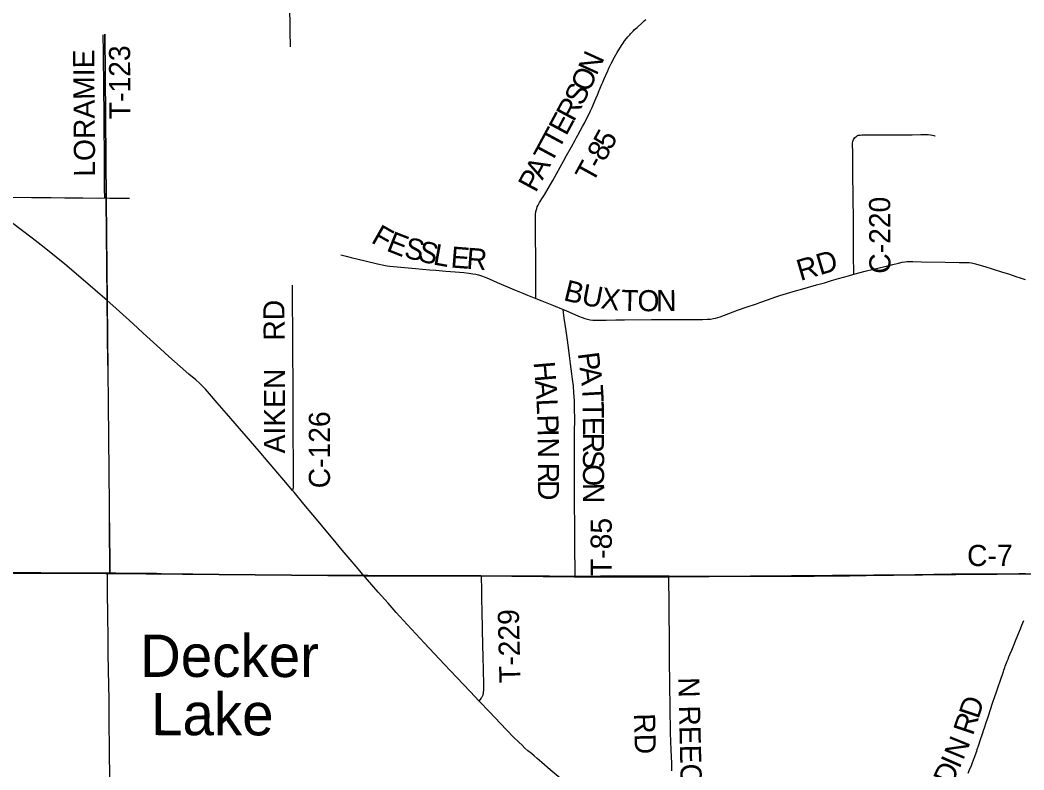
# Model space of a CAD drawing. Extents: x -87 to 2145, y -2128 to 440.
# Drawn here: x 215.6 to 286.8, y -467.2 to -413.9 of the extents above; entities that cross this region are included whole.
import ezdxf

# ---------------------------------------------------------------- set-up
doc = ezdxf.new("R2010")
doc.units = 0
for name, color, linetype in [('GM_X_Adjacent_County', 7, 'Continuous'), ('GM_X_County', 7, 'Continuous'), ('GM_X_County_Road', 7, 'Continuous'), ('GM_X_County_Road_Text', 7, 'Continuous'), ('GM_X_Minor_Lake_Text', 7, 'Continuous'), ('GM_X_State_Route', 7, 'Continuous'), ('GM_X_Township', 7, 'Continuous'), ('GM_X_Township_Road', 7, 'Continuous'), ('GM_X_Township_Road_Text', 7, 'Continuous')]:
    doc.layers.add(name, color=color, linetype=linetype)

msp = doc.modelspace()

# ---------------------------------------------------------------- linework, layer by layer
at = {"layer": 'GM_X_Adjacent_County'}
for points in [[(208.542, -453.167), (221.675, -453.226), (221.963, -453.23), (240.007, -453.386), (248.276, -453.386), (254.91, -453.454), (261.564, -453.461), (287.823, -453.254), (291.936, -453.162), (313.165, -452.741), (334.004, -452.531), (333.38, -455.988), (333.666, -457.29), (333.32, -460.854), (341.891, -461.324), (342.126, -461.349), (342.126, -234.663)], [(342.126, -655.29), (342.126, -461.349), (341.891, -461.324), (333.32, -460.854), (333.666, -457.29), (333.38, -455.988), (334.004, -452.531), (313.165, -452.741), (291.936, -453.162), (287.823, -453.254), (261.564, -453.461), (254.91, -453.454), (248.276, -453.386), (240.007, -453.386), (221.963, -453.23), (221.675, -453.226), (208.542, -453.167)]]:
    msp.add_lwpolyline(points, dxfattribs=at)
at = {"layer": 'GM_X_County'}
for points in [[(208.542, -453.167), (221.675, -453.226), (221.963, -453.23), (240.007, -453.386), (248.276, -453.386), (254.91, -453.454), (261.564, -453.461), (287.823, -453.254), (291.936, -453.162), (313.165, -452.741), (334.004, -452.531), (333.38, -455.988), (333.666, -457.29), (333.32, -460.854), (341.891, -461.324), (342.126, -461.349), (342.126, -234.663)], [(342.126, -655.29), (342.126, -461.349), (341.891, -461.324), (333.32, -460.854), (333.666, -457.29), (333.38, -455.988), (334.004, -452.531), (313.165, -452.741), (291.936, -453.162), (287.823, -453.254), (261.564, -453.461), (254.91, -453.454), (248.276, -453.386), (240.007, -453.386), (221.963, -453.23), (221.675, -453.226), (208.542, -453.167)]]:
    msp.add_lwpolyline(points, dxfattribs=at)
at = {"layer": 'GM_X_County_Road'}
for points in [[(234.769, -415.84), (234.757, -414.708), (234.756, -414.397), (234.745, -414.003), (234.73, -413.429), (234.73, -413.134), (234.722, -412.215), (234.71, -411.034), (234.691, -409.771), (234.687, -409.279), (234.685, -408.786), (234.679, -407.622), (234.67, -406.966), (234.652, -405.883), (234.651, -405.736), (234.651, -405.621), (234.651, -405.572), (234.655, -405.261), (234.657, -404.9), (234.646, -403.834), (234.638, -403.112), (234.63, -402.046), (234.616, -400.799), (234.603, -400.064)], [(274.746, -431.97), (274.739, -431.527), (274.737, -431.051), (274.736, -430.592), (274.735, -430.001), (274.733, -429.328), (274.72, -428.393), (274.702, -426.244), (274.687, -425.056), (274.678, -424.308), (274.679, -423.832), (274.675, -423.422), (274.676, -423.34), (274.66, -422.75), (274.664, -422.651), (274.679, -422.554), (274.701, -422.475), (274.734, -422.4), (274.777, -422.33), (274.828, -422.266), (274.888, -422.211), (274.956, -422.164), (275.015, -422.136), (275.092, -422.11), (275.189, -422.091), (275.32, -422.079), (275.697, -422.076), (276.041, -422.073), (276.37, -422.07), (277.239, -422.071), (277.895, -422.071), (278.371, -422.074), (278.896, -422.068), (279.504, -422.051), (279.799, -422.047), (280.028, -422.054), (280.191, -422.07), (280.321, -422.093), (280.432, -422.122), (280.492, -422.145), (280.52, -422.161)], [(212.954, -426.474), (213.44, -426.481), (214.933, -426.5), (216.409, -426.524), (216.819, -426.531), (217.803, -426.538), (218.771, -426.545), (220.034, -426.555), (221.117, -426.569), (221.601, -426.561)], [(221.601, -426.561), (221.945, -426.565), (222.961, -426.578), (223.347, -426.579)], [(238.351, -430.587), (238.442, -430.616), (238.728, -430.693), (239.078, -430.779), (240.066, -431.018), (240.959, -431.236), (241.391, -431.333), (241.634, -431.379), (241.83, -431.407), (242.091, -431.435), (242.598, -431.48), (243.644, -431.565), (244.64, -431.657), (245.098, -431.696), (245.801, -431.752), (246.455, -431.808), (247.076, -431.858), (247.434, -431.897), (247.708, -431.938), (247.916, -431.978), (248.106, -432.024), (248.34, -432.095), (248.601, -432.189), (248.873, -432.302), (249.442, -432.555), (250.178, -432.88), (250.677, -433.09), (251.253, -433.328), (251.588, -433.463), (251.831, -433.561), (252.178, -433.698)], [(274.746, -431.97), (275.559, -431.769), (276.142, -431.624), (276.645, -431.499), (276.98, -431.419), (277.52, -431.279), (277.918, -431.181), (278.19, -431.126), (278.366, -431.097), (278.512, -431.082), (278.658, -431.074), (278.936, -431.074), (279.559, -431.086), (281.229, -431.117), (282.214, -431.135), (282.506, -431.133), (282.735, -431.137), (282.929, -431.153), (283.107, -431.177), (283.378, -431.234), (283.615, -431.296), (284.053, -431.43), (284.646, -431.623), (285.24, -431.814), (285.789, -431.981), (286.239, -432.132), (286.553, -432.23), (286.912, -432.345)], [(254.135, -434.481), (254.313, -434.553), (255.215, -434.946), (255.476, -435.049), (255.663, -435.112), (255.855, -435.165), (256.049, -435.205), (256.23, -435.228), (256.444, -435.241), (256.74, -435.243), (257.167, -435.23), (257.872, -435.211), (258.478, -435.204), (260.397, -435.197), (262.5, -435.189), (263.459, -435.186), (264.006, -435.184), (264.335, -435.173), (264.582, -435.153), (264.794, -435.123), (264.939, -435.089), (265.098, -435.043), (265.254, -434.989), (265.87, -434.764), (266.502, -434.535), (267.121, -434.318), (267.832, -434.066), (268.074, -433.981), (268.688, -433.764), (269.136, -433.607), (269.509, -433.482), (269.978, -433.337), (270.434, -433.207), (271.129, -433.012), (272.108, -432.737), (272.659, -432.574), (273.164, -432.431), (273.668, -432.283), (274.361, -432.082), (274.746, -431.97)], [(234.923, -447.324), (234.963, -447.221), (234.977, -447.176), (234.985, -447.116), (234.99, -446.824), (234.979, -445.283), (234.972, -443.445), (234.963, -441.51), (234.958, -440.066), (234.955, -439.377), (234.946, -437.868), (234.942, -436.752), (234.933, -435.686), (234.93, -434.324), (234.924, -433.34), (234.922, -432.757)], [(252.178, -433.698), (252.609, -433.869), (253.432, -434.195), (254.135, -434.481)], [(208.614, -453.112), (209.098, -453.109), (209.54, -453.109), (210.246, -453.111), (211.033, -453.109), (211.525, -453.113), (211.82, -453.114), (212.312, -453.116), (212.706, -453.12), (213.493, -453.127), (214.001, -453.13), (214.772, -453.14), (215.248, -453.145), (216.396, -453.158), (217.052, -453.16), (217.38, -453.161), (218.184, -453.162), (218.823, -453.163), (219.709, -453.175), (220.005, -453.175), (220.496, -453.171), (220.889, -453.171), (221.365, -453.17), (221.786, -453.176)], [(208.614, -453.112), (209.098, -453.109), (209.54, -453.109), (210.246, -453.111), (211.033, -453.109), (211.525, -453.113), (211.82, -453.114), (212.312, -453.116), (212.706, -453.12), (213.493, -453.127), (214.001, -453.13), (214.772, -453.14), (215.248, -453.145), (216.396, -453.158), (217.052, -453.16), (217.38, -453.161), (218.184, -453.162), (218.823, -453.163), (219.709, -453.175), (220.005, -453.175), (220.496, -453.171), (220.889, -453.171), (221.365, -453.17), (221.786, -453.176)], [(221.786, -453.176), (222.053, -453.18), (222.381, -453.184), (223.135, -453.192), (223.561, -453.196), (223.906, -453.198), (224.185, -453.198), (224.737, -453.203), (225.266, -453.208), (225.609, -453.216), (227.119, -453.239), (227.844, -453.251), (228.574, -453.262), (228.754, -453.262), (228.901, -453.263), (229.459, -453.267), (230.312, -453.282), (231.28, -453.295), (231.706, -453.296), (232.132, -453.298), (232.559, -453.305), (232.969, -453.309), (233.559, -453.315), (234.281, -453.314), (234.674, -453.321), (235.183, -453.327), (236.216, -453.327), (236.873, -453.331), (237.611, -453.331), (238.119, -453.335), (238.628, -453.337), (239.66, -453.331), (239.791, -453.332), (239.947, -453.334)], [(221.786, -453.176), (222.053, -453.18), (222.076, -453.18)], [(222.076, -453.18), (222.381, -453.184), (223.135, -453.192), (223.561, -453.196), (223.906, -453.198), (224.185, -453.198), (224.737, -453.203), (225.266, -453.208), (225.609, -453.216), (227.119, -453.239), (227.844, -453.251), (228.574, -453.262), (228.754, -453.262), (228.901, -453.263), (229.459, -453.267), (230.312, -453.282), (231.28, -453.295), (231.706, -453.296), (232.132, -453.298), (232.559, -453.305), (232.969, -453.309), (233.559, -453.315), (234.281, -453.314), (234.674, -453.321), (235.183, -453.327), (236.216, -453.327), (236.873, -453.331), (237.611, -453.331), (238.119, -453.335), (238.628, -453.337), (239.66, -453.331), (239.791, -453.332), (239.947, -453.334)], [(239.947, -453.334), (240.253, -453.337), (241.546, -453.352), (242.071, -453.357), (242.514, -453.357), (242.99, -453.361), (243.859, -453.365), (244.548, -453.367), (245.401, -453.37), (246.336, -453.37), (247.435, -453.379), (248.058, -453.383), (248.377, -453.382)], [(239.947, -453.334), (240.253, -453.337), (241.546, -453.352), (242.071, -453.357), (242.514, -453.357), (242.99, -453.361), (243.859, -453.365), (244.548, -453.367), (245.401, -453.37), (246.336, -453.37), (247.435, -453.379), (248.058, -453.383), (248.377, -453.382)], [(248.377, -453.382), (248.648, -453.381), (249.649, -453.384), (250.502, -453.386), (251.584, -453.389), (252.569, -453.395), (253.159, -453.396), (253.897, -453.4), (254.636, -453.405), (254.98, -453.404)], [(248.377, -453.382), (248.648, -453.381), (249.649, -453.384), (250.502, -453.386), (251.584, -453.389), (252.569, -453.395), (253.159, -453.396), (253.897, -453.4), (254.636, -453.405), (254.98, -453.404)], [(254.98, -453.404), (255.177, -453.404), (255.571, -453.4), (256.768, -453.387), (257.702, -453.385), (258.736, -453.39), (259.769, -453.392), (260.982, -453.39), (261.618, -453.397)], [(254.98, -453.404), (255.177, -453.404), (255.571, -453.4), (256.768, -453.387), (257.702, -453.385), (258.736, -453.39), (259.769, -453.392), (260.982, -453.39), (261.618, -453.397)], [(261.618, -453.397), (261.688, -453.398), (262.426, -453.401), (263.049, -453.4), (264.952, -453.41), (265.674, -453.411), (267.314, -453.411), (268.561, -453.406), (268.971, -453.404), (269.889, -453.406), (270.742, -453.4), (271.365, -453.4), (271.94, -453.401), (272.497, -453.395), (273.17, -453.386), (273.809, -453.381), (274.432, -453.379), (275.072, -453.371), (275.629, -453.364), (276.744, -453.349), (277.564, -453.341), (278.68, -453.317), (279.122, -453.314), (279.385, -453.312), (279.631, -453.306), (279.828, -453.299), (280.221, -453.284), (280.433, -453.276), (280.646, -453.271), (281.122, -453.26), (281.679, -453.249), (282.268, -453.242), (282.465, -453.241), (282.612, -453.241), (282.76, -453.24), (283.121, -453.237), (283.678, -453.237), (284.219, -453.237), (284.597, -453.235), (285.302, -453.232), (285.778, -453.234), (285.974, -453.233), (286.466, -453.23), (286.941, -453.228)], [(261.618, -453.397), (261.688, -453.398), (262.426, -453.401), (263.049, -453.4), (264.952, -453.41), (265.674, -453.411), (267.314, -453.411), (268.561, -453.406), (268.971, -453.404), (269.889, -453.406), (270.742, -453.4), (271.365, -453.4), (271.94, -453.401), (272.497, -453.395), (273.17, -453.386), (273.809, -453.381), (274.432, -453.379), (275.072, -453.371), (275.629, -453.364), (276.744, -453.349), (277.564, -453.341), (278.68, -453.317), (279.122, -453.314), (279.385, -453.312), (279.631, -453.306), (279.828, -453.299), (280.221, -453.284), (280.433, -453.276), (280.646, -453.271), (281.122, -453.26), (281.679, -453.249), (282.268, -453.242), (282.465, -453.241), (282.612, -453.241), (282.76, -453.24), (283.121, -453.237), (283.678, -453.237), (284.219, -453.237), (284.597, -453.235), (285.302, -453.232), (285.778, -453.234), (285.974, -453.233), (286.466, -453.23), (286.941, -453.228)], [(282.854, -467.396), (282.993, -467.098), (283.071, -466.917), (283.177, -466.641), (283.295, -466.334), (283.468, -465.839), (283.51, -465.714), (283.619, -465.387), (283.722, -465.076), (283.902, -464.531), (283.953, -464.376), (284.039, -464.111), (284.114, -463.877), (284.252, -463.457), (284.299, -463.317), (284.599, -462.414), (284.748, -461.963), (284.841, -461.7), (284.966, -461.345), (285.179, -460.723), (285.32, -460.319), (285.367, -460.185), (285.404, -460.076), (285.443, -459.966), (285.472, -459.885), (285.5, -459.805), (285.545, -459.686), (285.59, -459.566), (285.641, -459.436), (285.691, -459.308), (285.758, -459.145), (285.825, -458.982), (285.955, -458.661), (286.097, -458.308), (286.223, -458.002), (286.39, -457.594), (286.502, -457.316), (286.576, -457.138), (286.678, -456.895), (286.819, -456.561)]]:
    msp.add_lwpolyline(points, dxfattribs=at)
at = {"layer": 'GM_X_State_Route'}
for points in [[(239.947, -453.334), (239.883, -453.258), (239.699, -453.038), (239.433, -452.725), (238.452, -451.556), (237.811, -450.788), (236.367, -449.066), (235.728, -448.296), (235.029, -447.448), (234.923, -447.324), (234.296, -446.587), (233.187, -445.29), (232.543, -444.546), (230.236, -441.857), (229.582, -441.099), (229.024, -440.455), (228.739, -440.139), (228.499, -439.893), (228.31, -439.711), (228.055, -439.481), (227.573, -439.061), (226.939, -438.515), (226.139, -437.81), (225.543, -437.27), (224.32, -436.152), (223.581, -435.478), (222.162, -434.186), (221.777, -433.845), (221.745, -433.817), (221.273, -433.41), (220.561, -432.803), (218.763, -431.271), (218.157, -430.77), (217.3, -430.082), (216.444, -429.419), (214.986, -428.302)], [(250.142, -464.366), (250.081, -464.304), (248.902, -463.052), (248.164, -462.274), (247.533, -461.604), (246.58, -460.597), (245.686, -459.649), (244.286, -458.169), (243.052, -456.847), (242.281, -455.977), (241.695, -455.32), (240.992, -454.534), (240.233, -453.662), (239.947, -453.334)], [(254.473, -468.215), (253.212, -467.147), (252.615, -466.643), (252.277, -466.357), (252.058, -466.17), (251.867, -466.007), (251.626, -465.799), (251.413, -465.61), (251.207, -465.417), (250.981, -465.205), (250.586, -464.82), (250.142, -464.366)]]:
    msp.add_lwpolyline(points, dxfattribs=at)
at = {"layer": 'GM_X_Township'}
for points in [[(92.095, -319.546), (90.326, -319.52), (90.326, -451.873), (98.227, -452.445), (101.35, -452.662), (107.813, -452.727), (113.202, -452.727), (114.73, -452.822), (141.984, -452.95), (161.811, -452.995), (181.93, -453.064), (195.32, -453.117), (208.542, -453.167), (221.675, -453.226), (221.963, -453.23), (221.928, -449.631)], [(221.819, -438.447), (221.705, -426.717), (221.59, -414.944)], [(221.59, -414.944), (221.705, -426.717), (221.963, -453.23)], [(221.928, -449.631), (221.963, -453.23), (240.007, -453.386), (248.276, -453.386), (254.91, -453.454), (261.564, -453.461), (287.823, -453.254)], [(208.542, -453.167), (221.675, -453.226), (221.963, -453.23), (240.007, -453.386), (248.276, -453.386), (254.91, -453.454), (261.564, -453.461), (287.823, -453.254), (291.936, -453.162), (313.165, -452.741), (334.004, -452.531), (333.38, -455.988), (333.666, -457.29), (333.32, -460.854), (333.294, -461.135), (333.2, -461.461), (332.933, -462.05), (332.682, -463.001), (332.537, -463.37), (331.871, -464.628), (331.581, -466.31), (331.554, -466.962), (331.412, -467.933)]]:
    msp.add_lwpolyline(points, dxfattribs=at)
at = {"layer": 'GM_X_Township_Road'}
for points in [[(252.178, -433.698), (252.185, -433.316), (252.189, -433.07), (252.187, -432.358), (252.186, -431.929), (252.183, -430.938), (252.173, -429.2), (252.169, -428.921), (252.162, -428.495), (252.158, -428.298), (252.158, -427.97), (252.167, -427.74), (252.194, -427.512), (252.247, -427.306), (252.287, -427.199), (252.347, -427.064), (252.441, -426.89), (252.664, -426.546), (252.794, -426.337), (253.062, -425.886), (253.385, -425.315), (253.647, -424.841), (254.17, -423.912), (254.369, -423.554), (254.71, -422.936), (254.967, -422.46), (255.068, -422.272), (255.162, -422.1), (255.496, -421.498), (255.638, -421.24), (255.791, -420.95), (255.964, -420.596), (256.066, -420.372), (256.156, -420.179), (256.22, -420.028), (256.322, -419.786), (256.46, -419.454), (256.574, -419.182), (256.632, -419.047), (256.872, -418.489), (256.939, -418.34), (256.982, -418.233), (257.041, -418.098), (257.152, -417.843), (257.292, -417.527), (257.376, -417.347), (257.537, -417.02), (257.549, -416.99), (257.578, -416.931), (257.771, -416.565), (257.959, -416.234), (258.14, -415.938), (258.322, -415.664), (258.376, -415.581), (258.383, -415.565), (258.431, -415.498), (258.436, -415.48), (258.505, -415.388), (258.512, -415.372), (258.603, -415.255), (258.615, -415.244), (258.718, -415.117), (258.73, -415.106), (258.805, -415.019), (258.849, -414.971), (258.903, -414.91), (259.094, -414.708), (259.198, -414.604), (259.371, -414.452), (259.749, -414.113), (259.883, -413.993), (259.987, -413.888)], [(221.601, -426.561), (221.587, -425.911), (221.578, -424.583), (221.571, -423.616), (221.57, -422.91), (221.564, -422.041), (221.557, -421.221), (221.548, -420.204), (221.535, -419.188), (221.531, -418.073), (221.514, -417.039), (221.498, -416.088), (221.484, -415.088), (221.484, -414.986)], [(254.98, -453.404), (254.978, -453.258), (254.978, -453.208), (254.973, -452.569), (254.964, -451.929), (254.951, -450.928), (254.949, -449.96), (254.942, -449.156), (254.94, -448.959), (254.939, -448.352), (254.936, -447.762), (254.931, -446.531), (254.932, -445.891), (254.927, -445.284), (254.927, -444.677), (254.94, -443.214), (254.944, -442.245), (254.936, -441.539), (254.917, -440.933), (254.888, -440.393), (254.849, -439.886), (254.792, -439.431), (254.745, -439.056), (254.652, -438.324), (254.6, -437.95), (254.496, -437.187), (254.402, -436.488), (254.333, -436.001), (254.203, -435.091), (254.158, -434.684), (254.135, -434.481)], [(222.036, -474.584), (222.034, -474.396), (222.013, -472.53), (221.984, -469.972), (221.974, -468.837), (221.941, -466.115), (221.913, -463.318), (221.902, -462.181), (221.863, -460.08), (221.837, -458.88), (221.828, -457.752), (221.817, -456.241), (221.8, -454.481), (221.786, -453.176)], [(248.164, -462.274), (248.253, -462.155), (248.299, -462.095), (248.338, -462.034), (248.366, -461.986), (248.395, -461.932), (248.418, -461.88), (248.438, -461.828), (248.451, -461.78), (248.464, -461.724), (248.475, -461.665), (248.481, -461.606), (248.488, -461.532), (248.492, -461.435), (248.486, -461.081), (248.46, -460.091), (248.438, -459.08), (248.414, -458.353), (248.368, -455.912), (248.356, -455.02), (248.345, -454.295), (248.33, -453.522), (248.33, -453.492), (248.333, -453.447), (248.343, -453.423), (248.356, -453.404), (248.377, -453.382)], [(261.844, -467.226), (261.824, -466.692), (261.781, -465.773), (261.743, -464.528), (261.706, -462.741), (261.691, -461.133), (261.669, -459.313), (261.664, -458.46), (261.663, -457.771), (261.662, -457.262), (261.655, -456.59), (261.642, -455.409), (261.637, -454.851), (261.632, -454.064), (261.618, -453.397)]]:
    msp.add_lwpolyline(points, dxfattribs=at)

# ---------------------------------------------------------------- texts
at = {"layer": 'GM_X_County_Road_Text'}
for s, rotation, p in [('C-220', 90.27377, (277.353, -431.934)), ('F', 330.49498, (240.425, -429.688)), ('E', 338.49731, (241.512, -430.285)), ('S', 346.1884, (242.765, -430.763)), ('S', 345.90384, (243.746, -431.004)), ('L', 349.84318, (244.838, -431.274)), ('E', 355.59334, (246.105, -431.493)), ('R', 355.53454, (247.223, -431.579)), ('RD', 16.46623, (270.954, -432.46)), ('B', 346.24301, (254.083, -433.806)), ('U', 349.07643, (255.358, -434.116)), ('X', 352.1615, (256.741, -434.381)), ('T', 358.4145, (258.227, -434.575)), ('O', 0.31252, (259.403, -434.607)), ('N', 0.30418, (260.723, -434.6)), ('RD', 90.49795, (234.365, -436.682)), ('AIKEN', 90, (234.386, -444.696)), ('C-126', 90, (237.577, -447.173)), ('C-7', 0.27014, (282.791, -452.695)), ('D', 71.67093, (283.588, -463.601)), ('R', 71.44222, (283.194, -464.776)), ('N', 67.94067, (282.507, -466.527)), ('I', 66.30233, (282.241, -467.134)), ('D', 66.06224, (281.702, -468.347))]:
    msp.add_text(s, height=1.5, rotation=rotation, dxfattribs=at).set_placement(p)
at = {"layer": 'GM_X_Minor_Lake_Text'}
for s, rotation, p in [('Decker', 359.91028, (224.091, -460.556)), ('Lake', 359.88753, (224.877, -464.696))]:
    msp.add_text(s, height=3.0003, rotation=rotation, dxfattribs=at).set_placement(p)
at = {"layer": 'GM_X_Township_Road_Text'}
for s, rotation, p in [('T-123', 90.28004, (223.417, -420.965)), ('LORAMIE', 90.45215, (220.917, -425.048)), ('N', 65.55001, (256.496, -417.922)), ('O', 65.62566, (255.952, -419.124)), ('S', 63.51767, (255.475, -420.084)), ('R', 61.9556, (254.875, -421.211)), ('E', 61.73257, (254.341, -422.205)), ('T', 61.73465, (253.809, -423.193)), ('5', 61.38634, (257.502, -423.232)), ('T', 61.73884, (253.278, -424.181)), ('8', 61.21497, (257.054, -424.046)), ('T', 61.18911, (256.216, -425.57)), ('-', 61.19421, (256.757, -424.587)), ('A', 61.7323, (252.653, -425.344)), ('P', 61.73689, (252.174, -426.235)), ('P', 277.32776, (255.158, -437.594)), ('H', 274.91279, (252.021, -438.225)), ('A', 276.85371, (255.287, -438.594)), ('A', 274.14545, (252.133, -439.534)), ('T', 273.36609, (255.443, -439.881)), ('L', 272.55937, (252.228, -440.84)), ('T', 270.56144, (255.508, -440.981)), ('P', 271.86769, (252.278, -441.956)), ('E', 270.17572, (255.519, -442.101)), ('I', 270.90555, (252.311, -442.961)), ('N', 270.43715, (252.321, -443.574)), ('R', 270.17174, (255.522, -443.223)), ('S', 270.17106, (255.526, -444.455)), ('R', 270.19125, (252.332, -445.354)), ('O', 270.17122, (255.529, -445.467)), ('D', 270.18944, (252.336, -446.586)), ('N', 270.17122, (255.533, -446.787)), ('T-85', 90, (257.573, -453.399)), ('T-229', 91.39557, (251.103, -460.971)), ('N REECE', 271.32236, (262.291, -460.601)), ('RD', 271.45715, (259.145, -463.166))]:
    msp.add_text(s, height=1.5, rotation=rotation, dxfattribs=at).set_placement(p)

doc.saveas('drawing.dxf')
